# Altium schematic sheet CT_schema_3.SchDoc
size 188 x 165 mm
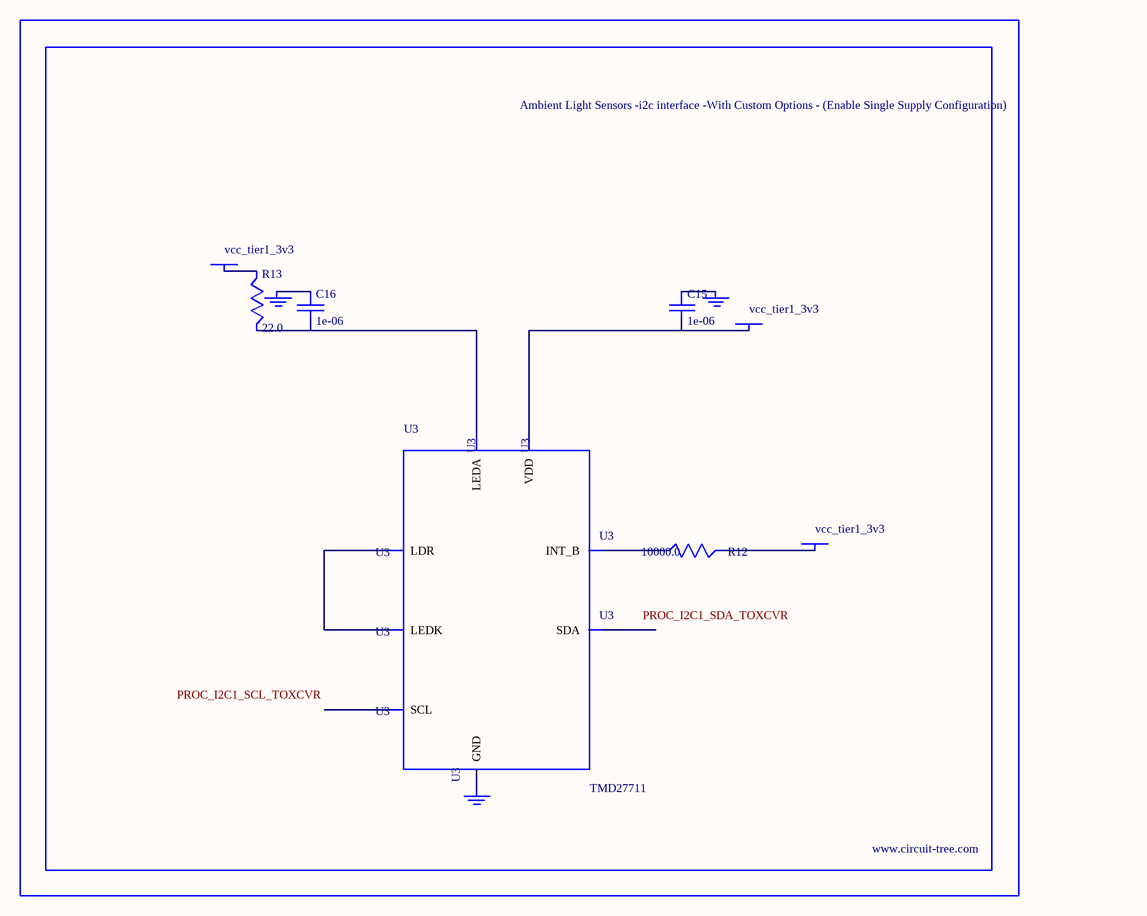
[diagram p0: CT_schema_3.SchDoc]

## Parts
BORDER2  (no value)
C15  1e-06  [C0603]
C16  1e-06  [C0603]
GND_INSTANCE_2_0  (no value)
GND_INSTANCE_2_1  (no value)
GND_INSTANCE_2_2  (no value)
POWER_INSTANCE_2_0  vcc_tier1_3v3
POWER_INSTANCE_2_1  vcc_tier1_3v3
POWER_INSTANCE_2_2  vcc_tier1_3v3
R12  10000.0  [R0603]
R13  22.0  [R0603]
U3  TMD27711  [SMD-8]

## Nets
NetC15_1: C15.1 GND_INSTANCE_2_0.0(GND)
NetC15_2: C15.2 POWER_INSTANCE_2_0.0(PWR) U3.1(VDD)
NetC16_1: C16.1 GND_INSTANCE_2_1.0(GND)
NetC16_2: C16.2 R13.2 U3.4(LEDA)
NetGND_INSTANCE_2_2_0: GND_INSTANCE_2_2.0(GND) U3.3(GND)
NetPOWER_INSTANCE_2_1_0: POWER_INSTANCE_2_1.0(PWR) R13.1
NetPOWER_INSTANCE_2_2_0: POWER_INSTANCE_2_2.0(PWR) R12.2
NetR12_1: R12.1 U3.7(INT_B)
NetU3_5: U3.5(LEDK) U3.6(LDR)

Not connected (* = marked no-connect by the designer): U3 2(SCL) 8(SDA)

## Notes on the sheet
- Labels drawn without touching a wire or pin: PROC_I2C1_SCL_TOXCVR, PROC_I2C1_SDA_TOXCVR

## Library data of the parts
BORDER2 = BORDER_PAGE2
C15 C16 = C0603C105K3RACTU
GND_INSTANCE_2_0-GND_INSTANCE_2_2 = GND
POWER_INSTANCE_2_0-POWER_INSTANCE_2_2 = PWR
R12 = RC0603JR-0710KL
R13 = RC0603JR-0722RL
